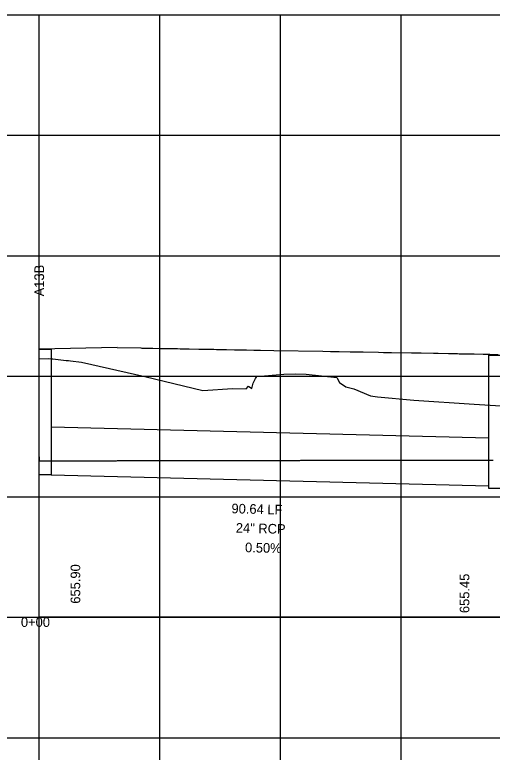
# Model space of a CAD drawing. Extents: x 2252703 to 2264864, y 13787568 to 13790989.
# Drawn here: x 2264558.6 to 2264657.5, y 13789162.9 to 13789315.9 of the extents above; entities that cross this region are included whole.
import ezdxf

# ---------------------------------------------------------------- set-up
doc = ezdxf.new("R2010")
doc.units = 0
for name, color, linetype in [('blank4', 7, 'Continuous'), ('BORD_grid_bottom_major_5int', 7, 'Continuous'), ('D_DRN_PROF_HGL', 7, 'Continuous'), ('D_PROF_1', 7, 'Continuous'), ('D_PROF_NOTES_1', 7, 'Continuous'), ('Default', 7, 'Continuous'), ('Drain_PipeInside', 7, 'Continuous'), ('E_Terrain', 7, 'Continuous'), ('Inlet', 7, 'Continuous'), ('z - Construction', 7, 'Continuous')]:
    doc.layers.add(name, color=color, linetype=linetype)

msp = doc.modelspace()

# ---------------------------------------------------------------- linework, layer by layer
at = {"layer": 'blank4'}
msp.add_lwpolyline([(2264563.67, 13789190.93), (2264563.67, 13789290.93), (2264744.95, 13789290.93), (2264744.95, 13789190.93)], close=True, dxfattribs=at)
at = {"layer": 'BORD_grid_bottom_major_5int'}
for p, q in [((2264413.67, 13789315.93), (2264763.67, 13789315.93)), ((2264563.67, 13789015.93), (2264563.67, 13789315.93)), ((2264588.67, 13789015.93), (2264588.67, 13789315.93)), ((2264613.67, 13789015.93), (2264613.67, 13789315.93)), ((2264638.67, 13789015.93), (2264638.67, 13789315.93)), ((2264413.67, 13789290.93), (2264763.67, 13789290.93)), ((2264413.67, 13789265.93), (2264763.67, 13789265.93)), ((2264413.67, 13789240.93), (2264763.67, 13789240.93)), ((2264413.67, 13789215.93), (2264763.67, 13789215.93)), ((2264413.67, 13789190.93), (2264763.67, 13789190.93)), ((2264413.67, 13789165.93), (2264763.67, 13789165.93))]:
    msp.add_line(p, q, dxfattribs=at)
at = {"layer": 'D_DRN_PROF_HGL'}
msp.add_lwpolyline([(2264563.67, 13789224.22), (2264563.67, 13789223.42), (2264563.73, 13789223.42), (2264563.84, 13789223.42), (2264563.95, 13789223.42), (2264564.06, 13789223.42), (2264564.17, 13789223.42), (2264564.28, 13789223.41), (2264564.4, 13789223.41), (2264564.52, 13789223.41), (2264564.64, 13789223.41), (2264564.76, 13789223.41), (2264564.88, 13789223.41), (2264565, 13789223.41), (2264565.12, 13789223.41), (2264565.25, 13789223.41), (2264565.37, 13789223.41), (2264565.5, 13789223.4), (2264565.63, 13789223.4), (2264565.76, 13789223.4), (2264565.89, 13789223.4), (2264566.02, 13789223.4), (2264566.15, 13789223.4), (2264566.28, 13789223.39), (2264566.42, 13789223.39), (2264566.55, 13789223.39), (2264566.69, 13789223.39), (2264566.82, 13789223.39), (2264566.96, 13789223.39), (2264567.1, 13789223.38), (2264567.24, 13789223.38), (2264567.38, 13789223.38), (2264567.52, 13789223.38), (2264567.66, 13789223.38), (2264567.8, 13789223.37), (2264567.94, 13789223.37), (2264568.09, 13789223.37), (2264568.23, 13789223.37), (2264568.38, 13789223.37), (2264568.52, 13789223.36), (2264568.67, 13789223.36), (2264568.82, 13789223.36), (2264568.96, 13789223.36), (2264569.11, 13789223.36), (2264569.26, 13789223.37), (2264569.41, 13789223.37), (2264569.56, 13789223.37), (2264569.71, 13789223.37), (2264569.86, 13789223.37), (2264570.01, 13789223.37), (2264570.17, 13789223.37), (2264570.32, 13789223.37), (2264570.47, 13789223.38), (2264570.63, 13789223.38), (2264570.78, 13789223.38), (2264570.93, 13789223.38), (2264571.09, 13789223.38), (2264571.25, 13789223.38), (2264571.4, 13789223.38), (2264571.56, 13789223.38), (2264571.72, 13789223.38), (2264571.87, 13789223.39), (2264572.03, 13789223.39), (2264572.19, 13789223.39), (2264572.35, 13789223.39), (2264572.51, 13789223.39), (2264572.67, 13789223.39), (2264572.83, 13789223.39), (2264572.99, 13789223.39), (2264573.15, 13789223.39), (2264573.31, 13789223.39), (2264573.48, 13789223.4), (2264573.64, 13789223.4), (2264573.8, 13789223.4), (2264573.96, 13789223.4), (2264574.13, 13789223.4), (2264574.29, 13789223.4), (2264574.46, 13789223.4), (2264574.62, 13789223.4), (2264574.78, 13789223.4), (2264574.95, 13789223.4), (2264575.12, 13789223.4), (2264575.28, 13789223.41), (2264575.45, 13789223.41), (2264575.61, 13789223.41), (2264575.78, 13789223.41), (2264575.95, 13789223.41), (2264576.12, 13789223.41), (2264576.28, 13789223.41), (2264576.45, 13789223.41), (2264576.62, 13789223.41), (2264576.79, 13789223.41), (2264576.96, 13789223.41), (2264577.13, 13789223.41), (2264577.3, 13789223.41), (2264577.47, 13789223.42), (2264577.64, 13789223.42), (2264577.81, 13789223.42), (2264577.98, 13789223.42), (2264578.15, 13789223.42), (2264578.32, 13789223.42), (2264578.49, 13789223.42), (2264578.66, 13789223.42), (2264578.83, 13789223.42), (2264579.01, 13789223.42), (2264579.18, 13789223.42), (2264579.35, 13789223.42), (2264579.52, 13789223.42), (2264579.7, 13789223.42), (2264579.87, 13789223.43), (2264580.04, 13789223.43), (2264580.22, 13789223.43), (2264580.39, 13789223.43), (2264580.57, 13789223.43), (2264580.74, 13789223.43), (2264580.92, 13789223.43), (2264581.09, 13789223.43), (2264581.27, 13789223.43), (2264581.44, 13789223.43), (2264581.62, 13789223.43), (2264581.79, 13789223.43), (2264581.97, 13789223.43), (2264582.14, 13789223.43), (2264582.32, 13789223.43), (2264582.5, 13789223.43), (2264582.67, 13789223.44), (2264582.85, 13789223.44), (2264583.03, 13789223.44), (2264583.2, 13789223.44), (2264583.38, 13789223.44), (2264583.56, 13789223.44), (2264583.74, 13789223.44), (2264583.92, 13789223.44), (2264584.09, 13789223.44), (2264584.27, 13789223.44), (2264584.45, 13789223.44), (2264584.63, 13789223.44), (2264584.81, 13789223.44), (2264584.99, 13789223.44), (2264585.17, 13789223.44), (2264585.35, 13789223.44), (2264585.52, 13789223.44), (2264585.7, 13789223.44), (2264585.88, 13789223.45), (2264586.06, 13789223.45), (2264586.24, 13789223.45), (2264586.42, 13789223.45), (2264586.6, 13789223.45), (2264586.79, 13789223.45), (2264586.97, 13789223.45), (2264587.15, 13789223.45), (2264587.33, 13789223.45), (2264587.51, 13789223.45), (2264587.69, 13789223.45), (2264587.87, 13789223.45), (2264588.05, 13789223.45), (2264588.24, 13789223.45), (2264588.42, 13789223.45), (2264588.6, 13789223.45), (2264588.78, 13789223.45), (2264588.96, 13789223.45), (2264589.15, 13789223.45), (2264589.33, 13789223.45), (2264589.51, 13789223.45), (2264589.69, 13789223.45), (2264589.88, 13789223.46), (2264590.06, 13789223.46), (2264590.24, 13789223.46), (2264590.43, 13789223.46), (2264590.61, 13789223.46), (2264590.79, 13789223.46), (2264590.98, 13789223.46), (2264591.16, 13789223.46), (2264591.34, 13789223.46), (2264591.53, 13789223.46), (2264591.71, 13789223.46), (2264591.9, 13789223.46), (2264592.08, 13789223.46), (2264592.27, 13789223.46), (2264592.45, 13789223.46), (2264592.63, 13789223.46), (2264592.82, 13789223.46), (2264593, 13789223.46), (2264593.19, 13789223.46), (2264593.37, 13789223.46), (2264593.56, 13789223.46), (2264593.74, 13789223.46), (2264593.93, 13789223.46), (2264594.12, 13789223.46), (2264594.3, 13789223.46), (2264594.49, 13789223.47), (2264594.67, 13789223.47), (2264594.86, 13789223.47), (2264595.04, 13789223.47), (2264595.23, 13789223.47), (2264595.42, 13789223.47), (2264595.6, 13789223.47), (2264595.79, 13789223.47), (2264595.98, 13789223.47), (2264596.16, 13789223.47), (2264596.35, 13789223.47), (2264596.54, 13789223.47), (2264596.72, 13789223.47), (2264596.91, 13789223.47), (2264597.1, 13789223.47), (2264597.28, 13789223.47), (2264597.47, 13789223.47), (2264597.66, 13789223.47), (2264597.85, 13789223.47), (2264598.03, 13789223.47), (2264598.22, 13789223.47), (2264598.41, 13789223.47), (2264598.6, 13789223.47), (2264598.78, 13789223.47), (2264598.97, 13789223.47), (2264599.16, 13789223.47), (2264599.35, 13789223.47), (2264599.54, 13789223.47), (2264599.72, 13789223.47), (2264599.91, 13789223.47), (2264600.1, 13789223.47), (2264600.29, 13789223.48), (2264600.48, 13789223.48), (2264600.67, 13789223.48), (2264600.86, 13789223.48), (2264601.04, 13789223.48), (2264601.23, 13789223.48), (2264601.42, 13789223.48), (2264601.61, 13789223.48), (2264601.8, 13789223.48), (2264601.99, 13789223.48), (2264602.18, 13789223.48), (2264602.37, 13789223.48), (2264602.56, 13789223.48), (2264602.75, 13789223.48), (2264602.94, 13789223.48), (2264603.12, 13789223.48), (2264603.31, 13789223.48), (2264603.5, 13789223.48), (2264603.69, 13789223.48), (2264603.88, 13789223.48), (2264604.07, 13789223.48), (2264604.26, 13789223.48), (2264604.45, 13789223.48), (2264604.64, 13789223.48), (2264604.83, 13789223.48), (2264605.02, 13789223.48), (2264605.21, 13789223.48), (2264605.4, 13789223.48), (2264605.59, 13789223.48), (2264605.78, 13789223.48), (2264605.98, 13789223.48), (2264606.17, 13789223.48), (2264606.36, 13789223.48), (2264606.55, 13789223.48), (2264606.74, 13789223.48), (2264606.93, 13789223.48), (2264607.12, 13789223.48), (2264607.31, 13789223.48), (2264607.5, 13789223.48), (2264607.69, 13789223.48), (2264607.88, 13789223.49), (2264608.07, 13789223.49), (2264608.27, 13789223.49), (2264608.46, 13789223.49), (2264608.65, 13789223.49), (2264608.84, 13789223.49), (2264609.03, 13789223.49), (2264609.22, 13789223.49), (2264609.41, 13789223.49), (2264609.61, 13789223.49), (2264609.8, 13789223.49), (2264609.99, 13789223.49), (2264610.18, 13789223.49), (2264610.37, 13789223.49), (2264610.56, 13789223.49), (2264610.76, 13789223.49), (2264610.95, 13789223.49), (2264611.14, 13789223.49), (2264611.33, 13789223.49), (2264611.52, 13789223.49), (2264611.72, 13789223.49), (2264611.91, 13789223.49), (2264612.1, 13789223.49), (2264612.29, 13789223.49), (2264612.48, 13789223.49), (2264612.68, 13789223.49), (2264612.87, 13789223.49), (2264613.06, 13789223.49), (2264613.25, 13789223.49), (2264613.45, 13789223.49), (2264613.64, 13789223.49), (2264613.83, 13789223.49), (2264614.03, 13789223.49), (2264614.22, 13789223.49), (2264614.41, 13789223.49), (2264614.6, 13789223.49), (2264614.8, 13789223.49), (2264614.99, 13789223.49), (2264615.18, 13789223.49), (2264615.37, 13789223.49), (2264615.57, 13789223.49), (2264615.76, 13789223.49), (2264615.95, 13789223.49), (2264616.15, 13789223.49), (2264616.34, 13789223.49), (2264616.53, 13789223.49), (2264616.73, 13789223.49), (2264616.92, 13789223.49), (2264617.11, 13789223.49), (2264617.31, 13789223.49), (2264617.5, 13789223.49), (2264617.69, 13789223.49), (2264617.89, 13789223.5), (2264618.08, 13789223.5), (2264618.27, 13789223.5), (2264618.47, 13789223.5), (2264618.66, 13789223.5), (2264618.86, 13789223.5), (2264619.05, 13789223.5), (2264619.24, 13789223.5), (2264619.44, 13789223.5), (2264619.63, 13789223.5), (2264619.82, 13789223.5), (2264620.02, 13789223.5), (2264620.21, 13789223.5), (2264620.41, 13789223.5), (2264620.6, 13789223.5), (2264620.79, 13789223.5), (2264620.99, 13789223.5), (2264621.18, 13789223.5), (2264621.38, 13789223.5), (2264621.57, 13789223.5), (2264621.77, 13789223.5), (2264621.96, 13789223.5), (2264622.15, 13789223.5), (2264622.35, 13789223.5), (2264622.54, 13789223.5), (2264622.74, 13789223.5), (2264622.93, 13789223.5), (2264623.13, 13789223.5), (2264623.32, 13789223.5), (2264623.52, 13789223.5), (2264623.71, 13789223.5), (2264623.9, 13789223.5), (2264624.1, 13789223.5), (2264624.29, 13789223.5), (2264624.49, 13789223.5), (2264624.68, 13789223.5), (2264624.88, 13789223.5), (2264625.07, 13789223.5), (2264625.27, 13789223.5), (2264625.46, 13789223.5), (2264625.66, 13789223.5), (2264625.85, 13789223.5), (2264626.05, 13789223.5), (2264626.24, 13789223.5), (2264626.44, 13789223.5), (2264626.63, 13789223.5), (2264626.83, 13789223.5), (2264627.02, 13789223.5), (2264627.22, 13789223.5), (2264627.41, 13789223.5), (2264627.61, 13789223.5), (2264627.8, 13789223.5), (2264628, 13789223.5), (2264628.19, 13789223.5), (2264628.39, 13789223.5), (2264628.58, 13789223.5), (2264628.78, 13789223.5), (2264628.98, 13789223.5), (2264629.17, 13789223.5), (2264629.37, 13789223.5), (2264629.56, 13789223.5), (2264629.76, 13789223.5), (2264629.95, 13789223.5), (2264630.15, 13789223.5), (2264630.34, 13789223.5), (2264630.54, 13789223.5), (2264630.74, 13789223.5), (2264630.93, 13789223.5), (2264631.13, 13789223.5), (2264631.32, 13789223.5), (2264631.52, 13789223.5), (2264631.71, 13789223.5), (2264631.91, 13789223.5), (2264632.11, 13789223.5), (2264632.3, 13789223.5), (2264632.5, 13789223.5), (2264632.69, 13789223.5), (2264632.89, 13789223.51), (2264633.08, 13789223.51), (2264633.28, 13789223.51), (2264633.48, 13789223.51), (2264633.67, 13789223.51), (2264633.87, 13789223.51), (2264634.06, 13789223.51), (2264634.26, 13789223.51), (2264634.46, 13789223.51), (2264634.65, 13789223.51), (2264634.85, 13789223.51), (2264635.05, 13789223.51), (2264635.24, 13789223.51), (2264635.44, 13789223.51), (2264635.63, 13789223.51), (2264635.83, 13789223.51), (2264636.03, 13789223.51), (2264636.22, 13789223.51), (2264636.42, 13789223.51), (2264636.62, 13789223.51), (2264636.81, 13789223.51), (2264637.01, 13789223.51), (2264637.2, 13789223.51), (2264637.4, 13789223.51), (2264637.6, 13789223.51), (2264637.79, 13789223.51), (2264637.99, 13789223.51), (2264638.19, 13789223.51), (2264638.38, 13789223.51), (2264638.58, 13789223.51), (2264638.78, 13789223.51), (2264638.97, 13789223.51), (2264639.17, 13789223.51), (2264639.37, 13789223.51), (2264639.56, 13789223.51), (2264639.76, 13789223.51), (2264639.96, 13789223.51), (2264640.15, 13789223.51), (2264640.35, 13789223.51), (2264640.55, 13789223.51), (2264640.74, 13789223.51), (2264640.94, 13789223.51), (2264641.14, 13789223.51), (2264641.33, 13789223.51), (2264641.53, 13789223.51), (2264641.73, 13789223.51), (2264641.92, 13789223.51), (2264642.12, 13789223.51), (2264642.32, 13789223.51), (2264642.52, 13789223.51), (2264642.71, 13789223.51), (2264642.91, 13789223.51), (2264643.11, 13789223.51), (2264643.3, 13789223.51), (2264643.5, 13789223.51), (2264643.7, 13789223.51), (2264643.89, 13789223.51), (2264644.09, 13789223.51), (2264644.29, 13789223.51), (2264644.49, 13789223.51), (2264644.68, 13789223.51), (2264644.88, 13789223.51), (2264645.08, 13789223.51), (2264645.27, 13789223.51), (2264645.47, 13789223.51), (2264645.67, 13789223.51), (2264645.87, 13789223.51), (2264646.06, 13789223.51), (2264646.26, 13789223.51), (2264646.46, 13789223.51), (2264646.66, 13789223.51), (2264646.85, 13789223.51), (2264647.05, 13789223.51), (2264647.25, 13789223.51), (2264647.44, 13789223.51), (2264647.64, 13789223.51), (2264647.84, 13789223.51), (2264648.04, 13789223.51), (2264648.23, 13789223.51), (2264648.43, 13789223.51), (2264648.63, 13789223.51), (2264648.83, 13789223.51), (2264649.02, 13789223.51), (2264649.22, 13789223.51), (2264649.42, 13789223.51), (2264649.62, 13789223.51), (2264649.81, 13789223.51), (2264650.01, 13789223.51), (2264650.21, 13789223.51), (2264650.41, 13789223.51), (2264650.6, 13789223.51), (2264650.8, 13789223.51), (2264651, 13789223.51), (2264651.2, 13789223.51), (2264651.4, 13789223.51), (2264651.59, 13789223.51), (2264651.79, 13789223.51), (2264651.99, 13789223.51), (2264652.19, 13789223.51), (2264652.38, 13789223.51), (2264652.58, 13789223.51), (2264652.78, 13789223.51), (2264652.98, 13789223.51), (2264653.18, 13789223.51), (2264653.37, 13789223.51), (2264653.57, 13789223.51), (2264653.77, 13789223.51), (2264653.97, 13789223.51), (2264654.16, 13789223.51), (2264654.36, 13789223.51), (2264654.56, 13789223.51), (2264654.76, 13789223.51), (2264654.96, 13789223.51), (2264655.15, 13789223.51), (2264655.35, 13789223.51), (2264655.55, 13789223.51), (2264655.75, 13789223.51), (2264655.95, 13789223.51), (2264656.14, 13789223.51), (2264656.34, 13789223.51), (2264656.54, 13789223.51), (2264656.74, 13789223.51), (2264656.94, 13789223.51), (2264657.13, 13789223.51), (2264657.33, 13789223.51), (2264657.53, 13789223.51), (2264657.73, 13789223.51)], dxfattribs=at)
at = {"layer": 'D_PROF_1'}
for p, q in [((2264579.8, 13789246.89), (2264563.67, 13789246.52)), ((2264612.28, 13789246.29), (2264622.46, 13789246.11))]:
    msp.add_line(p, q, dxfattribs=at)
for points in [[(2264579.8, 13789246.89), (2264584.73, 13789246.8), (2264584.92, 13789246.79), (2264585.54, 13789246.78), (2264586.44, 13789246.77), (2264586.72, 13789246.76), (2264587.18, 13789246.75), (2264588.67, 13789246.72), (2264590.4, 13789246.69), (2264590.93, 13789246.68), (2264592.02, 13789246.66), (2264592.35, 13789246.66), (2264592.86, 13789246.65), (2264594.52, 13789246.62), (2264594.69, 13789246.61), (2264594.74, 13789246.61), (2264596.73, 13789246.58), (2264597.32, 13789246.57), (2264599.05, 13789246.53), (2264599.56, 13789246.52), (2264599.59, 13789246.52), (2264599.72, 13789246.52), (2264599.88, 13789246.52), (2264600.43, 13789246.51), (2264602, 13789246.48), (2264602.46, 13789246.47), (2264604.15, 13789246.44), (2264604.64, 13789246.43), (2264604.99, 13789246.43), (2264606.2, 13789246.4), (2264606.63, 13789246.4), (2264608.13, 13789246.37), (2264608.62, 13789246.36), (2264608.77, 13789246.36), (2264609.55, 13789246.34), (2264612.28, 13789246.29)], [(2264622.46, 13789246.11), (2264622.46, 13789246.11), (2264622.47, 13789246.11), (2264624.01, 13789246.09), (2264624.45, 13789246.08), (2264625.03, 13789246.07), (2264625.19, 13789246.06), (2264625.84, 13789246.05), (2264628.08, 13789246.01), (2264628.19, 13789246.01), (2264628.58, 13789246.01), (2264628.67, 13789246), (2264629, 13789246), (2264629.71, 13789245.99), (2264629.92, 13789245.98), (2264630.83, 13789245.97), (2264633.95, 13789245.91), (2264635.02, 13789245.89), (2264635.33, 13789245.89), (2264635.36, 13789245.89), (2264635.47, 13789245.89), (2264636.7, 13789245.86), (2264640.81, 13789245.79), (2264641.77, 13789245.78), (2264642.06, 13789245.77), (2264642.85, 13789245.76), (2264645.39, 13789245.71), (2264645.48, 13789245.71), (2264645.75, 13789245.71), (2264646.18, 13789245.7), (2264646.31, 13789245.7), (2264648.52, 13789245.66), (2264649.23, 13789245.65), (2264649.51, 13789245.64), (2264650.37, 13789245.63), (2264650.7, 13789245.62), (2264651.71, 13789245.61), (2264652.68, 13789245.59), (2264653.81, 13789245.57), (2264653.81, 13789245.57), (2264655.64, 13789245.54), (2264655.93, 13789245.53), (2264656.02, 13789245.53), (2264656.2, 13789245.53), (2264656.72, 13789245.52), (2264656.72, 13789245.52), (2264656.72, 13789245.52), (2264656.98, 13789245.52), (2264657.07, 13789245.51), (2264658.75, 13789245.48)]]:
    msp.add_lwpolyline(points, dxfattribs=at)
at = {"layer": 'Drain_PipeInside'}
for p, q in [((2264566.17, 13789230.45), (2264656.81, 13789228.18)), ((2264566.17, 13789220.45), (2264656.81, 13789218.18))]:
    msp.add_line(p, q, dxfattribs=at)
at = {"layer": 'E_Terrain'}
msp.add_lwpolyline([(2264563.67, 13789244.53), (2264565.56, 13789244.63), (2264565.62, 13789244.62), (2264566.17, 13789244.56), (2264566.17, 13789244.56), (2264566.48, 13789244.53), (2264569.27, 13789244.23), (2264569.73, 13789244.18), (2264570.18, 13789244.14), (2264572.45, 13789243.89), (2264585.54, 13789240.86), (2264597.54, 13789238.01), (2264603.69, 13789238.36), (2264606.53, 13789238.33), (2264607.02, 13789238.87), (2264607.75, 13789238.37), (2264608.01, 13789239.48), (2264608.48, 13789240.44), (2264608.78, 13789240.89), (2264614.39, 13789241.36), (2264616.75, 13789241.45), (2264619.02, 13789241.35), (2264625.36, 13789240.65), (2264625.93, 13789239.67), (2264627.18, 13789238.77), (2264628.86, 13789238.31), (2264632.35, 13789236.85), (2264633.75, 13789236.66), (2264641.32, 13789236), (2264653.81, 13789235.15), (2264653.81, 13789235.15), (2264659.31, 13789234.79)], dxfattribs=at)
at = {"layer": 'Inlet'}
for points in [[(2264563.67, 13789246.52), (2264566.17, 13789246.52), (2264566.17, 13789220.45), (2264563.67, 13789220.45)], [(2264656.81, 13789245.32), (2264665.5, 13789245.32), (2264665.5, 13789217.68), (2264656.81, 13789217.68)]]:
    msp.add_lwpolyline(points, close=True, dxfattribs=at)
at = {"layer": 'z - Construction'}
for p, q in [((2264563.67, 13789265.93), (2264744.95, 13789265.93)), ((2264563.67, 13789240.93), (2264744.95, 13789240.93)), ((2264563.67, 13789215.93), (2264744.95, 13789215.93))]:
    msp.add_line(p, q, dxfattribs=at)

# ---------------------------------------------------------------- texts
at = {"layer": 'D_PROF_NOTES_1'}
for s, rotation, p in [('A13B', 90, (2264564.67, 13789257.51)), ('90.64 LF', 358.5679, (2264603.49, 13789212.51)), ('24" RCP', 358.5679, (2264604.39, 13789208.49)), ('0.50%', 358.5679, (2264606.3, 13789204.44)), ('655.90', 90, (2264572.17, 13789193.75)), ('655.45', 90, (2264652.81, 13789191.8))]:
    msp.add_text(s, height=2, rotation=rotation, dxfattribs=at).set_placement(p)
at = {"layer": 'Default'}
msp.add_text('0+00', height=2, dxfattribs=at).set_placement((2264559.87, 13789188.93))

doc.saveas('drawing.dxf')
